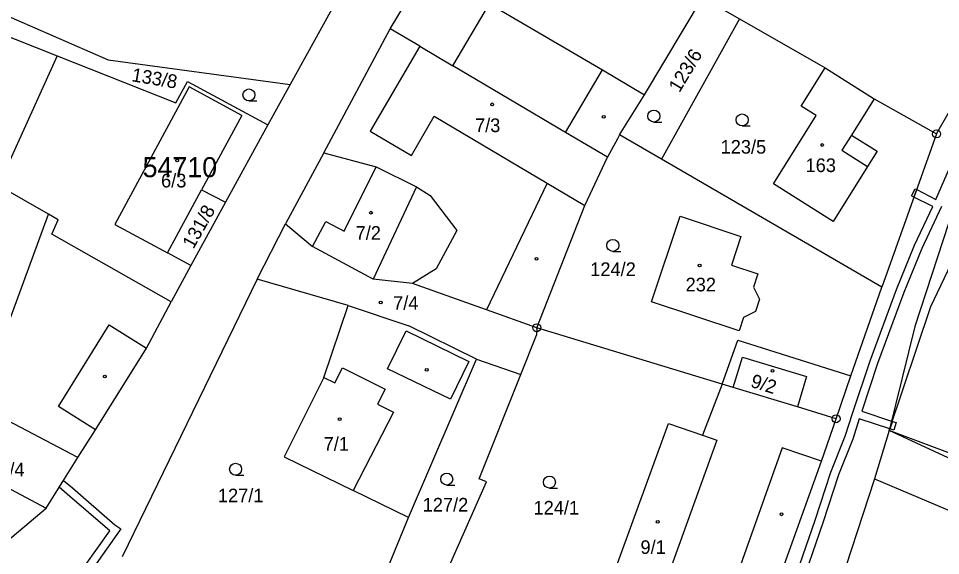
# Model space of a CAD drawing. Extents: x -747333 to -745433, y -1133152 to -1130600.
# Drawn here: x -746442.1 to -746327.1, y -1132019.6 to -1131952.5 of the extents above; entities that cross this region are included whole.
import ezdxf

# ---------------------------------------------------------------- set-up
doc = ezdxf.new("R2010")
doc.units = 0
for name, color, linetype in [('Vrstva 1', 7, 'Continuous'), ('Vrstva 18', 7, 'Continuous'), ('Vrstva 19', 7, 'Continuous'), ('Vrstva 24', 7, 'Continuous'), ('Vrstva 25', 7, 'Continuous'), ('Vrstva 3', 7, 'Continuous'), ('Vrstva 30', 7, 'Continuous'), ('Vrstva 37', 7, 'Continuous'), ('Vrstva 4', 7, 'Continuous'), ('Vrstva 53', 7, 'Continuous'), ('Vrstva 6', 7, 'Continuous'), ('Vrstva 62', 7, 'Continuous')]:
    doc.layers.add(name, color=color, linetype=linetype)

msp = doc.modelspace()

# ---------------------------------------------------------------- linework, layer by layer
at = {"layer": 'Vrstva 1'}
msp.add_line((-746311.75, -1132014.1), (-746333.47, -1132003.98), dxfattribs=at)
for points in [[(-746395.75, -1131953.81), (-746381.8, -1131930.69)], [(-746399.53, -1131945), (-746408.25, -1131960.77)], [(-746453.89, -1131947.67), (-746430.93, -1131957.68)], [(-746455.89, -1131949.78), (-746437.32, -1131957.2)], [(-746387.94, -1131958.43), (-746383.37, -1131950.7)], [(-746383.37, -1131950.7), (-746369.24, -1131958.95)], [(-746364, -1131962.05), (-746356.8, -1131949.89)], [(-746356.8, -1131949.89), (-746352.16, -1131952.55)], [(-746352.16, -1131952.55), (-746361.91, -1131970.09)], [(-746352.16, -1131952.55), (-746341.49, -1131958.67)], [(-746404.04, -1131969.28), (-746395.75, -1131953.81)], [(-746392.06, -1131955.99), (-746395.75, -1131953.81)], [(-746392.06, -1131955.99), (-746387.94, -1131958.43)], [(-746327.57, -1131966.94), (-746321.42, -1131956.19)], [(-746437.32, -1131957.2), (-746444.69, -1131973.38)], [(-746437.32, -1131957.2), (-746422.49, -1131963.07)], [(-746430.93, -1131957.68), (-746408.25, -1131960.77)], [(-746344.48, -1131963.46), (-746341.49, -1131958.67)], [(-746341.49, -1131958.67), (-746335.36, -1131962.56)], [(-746369.24, -1131958.95), (-746364, -1131962.05)], [(-746422.49, -1131963.07), (-746421.04, -1131960.39)], [(-746421.04, -1131960.39), (-746411.04, -1131965.81)], [(-746408.25, -1131960.77), (-746411.04, -1131965.81)], [(-746367.12, -1131967.06), (-746364, -1131962.05)], [(-746335.36, -1131962.56), (-746338.2, -1131967.09)], [(-746335.36, -1131962.56), (-746327.57, -1131966.94)], [(-746342.61, -1131964.63), (-746344.48, -1131963.46)], [(-746347.93, -1131973.15), (-746342.61, -1131964.63)], [(-746411.04, -1131965.81), (-746416.31, -1131975.44)], [(-746367.37, -1131967.53), (-746368.62, -1131969.86)], [(-746367.12, -1131967.06), (-746367.37, -1131967.53)], [(-746361.91, -1131970.09), (-746367.12, -1131967.06)], [(-746338.2, -1131967.09), (-746334.98, -1131969.11)], [(-746327.57, -1131966.94), (-746334.41, -1131986.06)], [(-746334.98, -1131969.11), (-746336.17, -1131971)], [(-746404.04, -1131969.28), (-746408.81, -1131978.18)], [(-746404.04, -1131969.28), (-746397.49, -1131971.05)], [(-746371.48, -1131975.87), (-746368.62, -1131969.86)], [(-746334.41, -1131986.06), (-746361.91, -1131970.09)], [(-746397.49, -1131971.05), (-746392.46, -1131973.55)], [(-746336.17, -1131971), (-746340.47, -1131977.86)], [(-746438.41, -1131976.96), (-746444.69, -1131973.38)], [(-746392.46, -1131973.55), (-746390.76, -1131974.61)], [(-746340.47, -1131977.86), (-746347.93, -1131973.15)], [(-746423.54, -1131981.79), (-746419.29, -1131973.93)], [(-746419.29, -1131973.93), (-746416.31, -1131975.44)], [(-746390.76, -1131974.61), (-746387.42, -1131978.99)], [(-746416.31, -1131975.44), (-746420.64, -1131983.36)], [(-746377.47, -1131991.14), (-746371.48, -1131975.87)], [(-746437.18, -1131977.66), (-746438.41, -1131976.96)], [(-746437.98, -1131979.44), (-746437.18, -1131977.66)], [(-746412.35, -1131985.06), (-746408.81, -1131978.18)], [(-746408.81, -1131978.18), (-746405.47, -1131981.01)], [(-746363.14, -1131987.9), (-746359.57, -1131977.21)], [(-746359.57, -1131977.21), (-746351.98, -1131979.75)], [(-746423.09, -1131987.89), (-746437.98, -1131979.44)], [(-746387.42, -1131978.99), (-746390.02, -1131983.77)], [(-746351.98, -1131979.75), (-746353.17, -1131983.31)], [(-746328.28, -1131988.49), (-746324.05, -1131979.6)], [(-746420.64, -1131983.36), (-746423.54, -1131981.79)], [(-746397.86, -1131985.09), (-746405.47, -1131981.01)], [(-746420.64, -1131983.36), (-746423.09, -1131987.89)], [(-746390.02, -1131983.77), (-746392.96, -1131985.62)], [(-746353.17, -1131983.31), (-746349.86, -1131984.42)], [(-746412.35, -1131985.06), (-746429.19, -1132019.77)], [(-746400.99, -1131988.36), (-746412.35, -1131985.06)], [(-746392.96, -1131985.62), (-746397.86, -1131985.09)], [(-746349.86, -1131984.42), (-746350.41, -1131986.06)], [(-746383.74, -1131988.91), (-746392.96, -1131985.62)], [(-746350.41, -1131986.06), (-746349.66, -1131987.58)], [(-746338.25, -1131997.16), (-746334.41, -1131986.06)], [(-746426.16, -1131993.7), (-746423.09, -1131987.89)], [(-746404.05, -1131997.34), (-746400.99, -1131988.36)], [(-746400.99, -1131988.36), (-746393.44, -1131990.91)], [(-746352.22, -1131991.54), (-746363.14, -1131987.9)], [(-746349.66, -1131987.58), (-746350.17, -1131989.11)], [(-746333.47, -1132003.98), (-746328.28, -1131988.49)], [(-746377.47, -1131991.14), (-746383.74, -1131988.91)], [(-746350.17, -1131989.11), (-746351.68, -1131989.88)], [(-746384.98, -1131995.05), (-746393.44, -1131990.91)], [(-746351.68, -1131989.88), (-746352.22, -1131991.54)], [(-746379.47, -1131997), (-746377.51, -1131992.07)], [(-746377.47, -1131991.14), (-746377.51, -1131992.07)], [(-746354.34, -1131998.17), (-746377.47, -1131991.14)], [(-746354.34, -1131998.17), (-746352.35, -1131992.71)], [(-746352.35, -1131992.71), (-746338.25, -1131997.16)], [(-746432.53, -1132003.87), (-746426.16, -1131993.7)], [(-746393.46, -1132014.85), (-746384.98, -1131995.05)], [(-746384.98, -1131995.05), (-746379.47, -1131997)], [(-746404.05, -1131997.34), (-746409, -1132007.27)], [(-746384.66, -1132010), (-746379.47, -1131997)], [(-746340.11, -1132002.51), (-746338.25, -1131997.16)], [(-746354.34, -1131998.17), (-746356.76, -1132004.57)], [(-746352.95, -1131998.59), (-746354.34, -1131998.17)], [(-746344.93, -1132001.03), (-746352.95, -1131998.59)], [(-746340.11, -1132002.51), (-746344.93, -1132001.03)], [(-746434.75, -1132007.36), (-746445.14, -1132001.9)], [(-746367.57, -1132021.06), (-746361.01, -1132003.1)], [(-746361.01, -1132003.1), (-746356.76, -1132004.57)], [(-746341.94, -1132007.79), (-746340.11, -1132002.51)], [(-746434.75, -1132007.36), (-746432.53, -1132003.87)], [(-746333.47, -1132003.98), (-746335.32, -1132010.03)], [(-746311.98, -1132012.06), (-746333.47, -1132003.98)], [(-746438.69, -1132013.68), (-746434.75, -1132007.36)], [(-746409, -1132007.27), (-746400.37, -1132011.48)], [(-746348.1, -1132024.97), (-746341.94, -1132007.79)], [(-746448.81, -1132008.32), (-746438.69, -1132013.68)], [(-746391.22, -1132027.33), (-746383.75, -1132010.4)], [(-746383.75, -1132010.4), (-746384.66, -1132010)], [(-746335.32, -1132010.03), (-746340.35, -1132025.42)], [(-746335.32, -1132010.03), (-746323.11, -1132015.17)], [(-746393.46, -1132014.85), (-746400.37, -1132011.48)], [(-746449.32, -1132022.63), (-746438.69, -1132013.68)], [(-746397.45, -1132024.58), (-746393.46, -1132014.85)]]:
    msp.add_lwpolyline(points, dxfattribs=at)
at = {"layer": 'Vrstva 24'}
for p, q in [((-746327.62, -1131966.94), (-746327.52, -1131966.94)), ((-746377.52, -1131991.14), (-746377.42, -1131991.14)), ((-746340.16, -1132002.51), (-746340.06, -1132002.51))]:
    msp.add_line(p, q, dxfattribs=at)
for centre in [(-746327.57, -1131966.94), (-746377.47, -1131991.14), (-746340.11, -1132002.51)]:
    msp.add_circle(centre, 0.499289, dxfattribs=at)
at = {"layer": 'Vrstva 25'}
for p, q in [((-746413.38, -1131962.82), (-746412.38, -1131962.82)), ((-746362.85, -1131965.46), (-746361.85, -1131965.46)), ((-746351.83, -1131965.94), (-746350.83, -1131965.94)), ((-746367.97, -1131981.61), (-746366.97, -1131981.61)), ((-746415.04, -1132009.56), (-746414.04, -1132009.56)), ((-746388.7, -1132010.79), (-746387.7, -1132010.79)), ((-746375.88, -1132011.17), (-746374.88, -1132011.17))]:
    msp.add_line(p, q, dxfattribs=at)
for centre, radius in [((-746413.38, -1131962.07), 0.75), ((-746383.02, -1131963.25), 0.174503), ((-746362.85, -1131964.71), 0.75), ((-746351.83, -1131965.19), 0.75), ((-746369.11, -1131964.8), 0.174503), ((-746341.85, -1131968.32), 0.174503), ((-746422.33, -1131970.25), 0.174503), ((-746398.15, -1131976.77), 0.174503), ((-746367.97, -1131980.86), 0.75), ((-746377.5, -1131982.53), 0.174503), ((-746357.14, -1131983.37), 0.174503), ((-746391.2, -1131996.4), 0.174503), ((-746348.05, -1131996.51), 0.174503), ((-746431.36, -1131997.23), 0.174503), ((-746402.06, -1132002.57), 0.174503), ((-746415.04, -1132008.81), 0.75), ((-746388.7, -1132010.04), 0.75), ((-746375.88, -1132010.42), 0.75), ((-746346.93, -1132014.44), 0.174503), ((-746362.37, -1132015.38), 0.174503)]:
    msp.add_circle(centre, radius, dxfattribs=at)
at = {"layer": 'Vrstva 3'}
for points in [[(-746392.06, -1131955.99), (-746398.27, -1131966.61)], [(-746392.06, -1131955.99), (-746387.94, -1131958.43)], [(-746373.86, -1131966.76), (-746387.94, -1131958.43)], [(-746344.48, -1131963.46), (-746341.49, -1131958.67)], [(-746341.49, -1131958.67), (-746335.36, -1131962.56)], [(-746420.84, -1131961.07), (-746430.12, -1131978.23)], [(-746414.26, -1131964.63), (-746420.84, -1131961.07)], [(-746335.36, -1131962.56), (-746338.2, -1131967.09)], [(-746342.61, -1131964.63), (-746344.48, -1131963.46)], [(-746414.26, -1131964.63), (-746419.29, -1131973.93)], [(-746393.11, -1131969.63), (-746390.26, -1131964.74)], [(-746390.26, -1131964.74), (-746376.15, -1131973.1)], [(-746347.93, -1131973.15), (-746342.61, -1131964.63)], [(-746398.27, -1131966.61), (-746393.11, -1131969.63)], [(-746368.62, -1131969.86), (-746373.86, -1131966.76)], [(-746338.2, -1131967.09), (-746339.38, -1131968.98)], [(-746339.38, -1131968.98), (-746336.17, -1131971)], [(-746371.48, -1131975.87), (-746368.62, -1131969.86)], [(-746401.49, -1131979.09), (-746397.49, -1131971.05)], [(-746397.49, -1131971.05), (-746392.46, -1131973.55)], [(-746336.17, -1131971), (-746340.47, -1131977.86)], [(-746438.41, -1131976.96), (-746444.69, -1131973.38)], [(-746392.46, -1131973.55), (-746397.86, -1131985.09)], [(-746376.15, -1131973.1), (-746371.48, -1131975.87)], [(-746340.47, -1131977.86), (-746347.93, -1131973.15)], [(-746423.54, -1131981.79), (-746419.29, -1131973.93)], [(-746446.26, -1131998.3), (-746438.41, -1131976.96)], [(-746430.12, -1131978.23), (-746423.54, -1131981.79)], [(-746405.47, -1131981.01), (-746403.78, -1131977.86)], [(-746403.78, -1131977.86), (-746401.49, -1131979.09)], [(-746363.14, -1131987.9), (-746359.57, -1131977.21)], [(-746359.57, -1131977.21), (-746351.98, -1131979.75)], [(-746351.98, -1131979.75), (-746353.17, -1131983.31)], [(-746397.86, -1131985.09), (-746405.47, -1131981.01)], [(-746353.17, -1131983.31), (-746349.86, -1131984.42)], [(-746349.86, -1131984.42), (-746350.41, -1131986.06)], [(-746350.41, -1131986.06), (-746349.66, -1131987.58)], [(-746352.22, -1131991.54), (-746363.14, -1131987.9)], [(-746349.66, -1131987.58), (-746350.17, -1131989.11)], [(-746350.17, -1131989.11), (-746351.68, -1131989.88)], [(-746351.68, -1131989.88), (-746352.22, -1131991.54)], [(-746352.95, -1131998.59), (-746351.8, -1131994.81)], [(-746351.8, -1131994.81), (-746343.78, -1131997.25)], [(-746402.65, -1131998.04), (-746401.71, -1131996.16)], [(-746401.71, -1131996.16), (-746396.39, -1131998.81)], [(-746404.05, -1131997.34), (-746409, -1132007.27)], [(-746404.05, -1131997.34), (-746402.65, -1131998.04)], [(-746343.78, -1131997.25), (-746344.93, -1132001.03)], [(-746396.39, -1131998.81), (-746397.32, -1132000.69)], [(-746344.93, -1132001.03), (-746352.95, -1131998.59)], [(-746397.32, -1132000.69), (-746395.34, -1132001.68)], [(-746434.75, -1132007.36), (-746445.14, -1132001.9)], [(-746395.34, -1132001.68), (-746400.37, -1132011.48)], [(-746367.57, -1132021.06), (-746361.01, -1132003.1)], [(-746361.01, -1132003.1), (-746356.76, -1132004.57)], [(-746356.76, -1132004.57), (-746354.99, -1132005.18)], [(-746354.99, -1132005.18), (-746363.4, -1132028.51)], [(-746438.69, -1132013.68), (-746434.75, -1132007.36)], [(-746409, -1132007.27), (-746400.37, -1132011.48)], [(-746448.81, -1132008.32), (-746438.69, -1132013.68)]]:
    msp.add_lwpolyline(points, dxfattribs=at)
at = {"layer": 'Vrstva 30'}
for points in [[(-746327.64, -1131975.11), (-746325.26, -1131969.58)], [(-746330.69, -1131974.68), (-746330.24, -1131973.79)], [(-746330.39, -1131974.83), (-746330.69, -1131974.68)], [(-746330.39, -1131974.83), (-746330.05, -1131973.88)], [(-746330.05, -1131973.88), (-746330.39, -1131974.83)], [(-746328.05, -1131976.02), (-746330.39, -1131974.83)], [(-746330.24, -1131973.79), (-746330.05, -1131973.88)], [(-746330.05, -1131973.88), (-746327.64, -1131975.11)], [(-746330.33, -1131980.84), (-746328.05, -1131976.02)], [(-746326.94, -1131976.01), (-746329.41, -1131981.24)], [(-746332.57, -1131986.38), (-746330.33, -1131980.84)], [(-746329.41, -1131981.24), (-746331.64, -1131986.74)], [(-746335.87, -1131995.26), (-746332.57, -1131986.38)], [(-746331.64, -1131986.74), (-746334.93, -1131995.6)], [(-746338, -1132001.74), (-746335.87, -1131995.26)], [(-746334.93, -1131995.6), (-746336.9, -1132001.58)], [(-746338.97, -1132004.7), (-746338, -1132001.74)], [(-746336.9, -1132001.58), (-746333.18, -1132002.8)], [(-746337.21, -1132002.53), (-746338.03, -1132005.04)], [(-746333.42, -1132003.77), (-746337.21, -1132002.53)], [(-746333.08, -1132002.83), (-746333.4, -1132003.78)], [(-746333.4, -1132003.78), (-746333.08, -1132002.83)], [(-746333.18, -1132002.8), (-746333.08, -1132002.83)], [(-746333.08, -1132002.83), (-746332.59, -1132002.99)], [(-746332.59, -1132002.99), (-746332.9, -1132003.94)], [(-746340.76, -1132009.16), (-746338.97, -1132004.7)], [(-746333.4, -1132003.78), (-746333.42, -1132003.77)], [(-746332.9, -1132003.94), (-746333.4, -1132003.78)], [(-746338.03, -1132005.04), (-746339.82, -1132009.5)], [(-746342.71, -1132015.19), (-746340.76, -1132009.16)], [(-746437.06, -1132011.07), (-746436.53, -1132010.21)], [(-746436.53, -1132010.21), (-746435.42, -1132011.15)], [(-746339.82, -1132009.5), (-746341.75, -1132015.49)], [(-746436.06, -1132011.91), (-746437.06, -1132011.07)], [(-746435.42, -1132011.15), (-746430.12, -1132015.75)], [(-746430.76, -1132016.51), (-746436.06, -1132011.91)], [(-746429.36, -1132016.26), (-746432.96, -1132021.32)], [(-746430.12, -1132015.75), (-746429.36, -1132016.26)], [(-746345.75, -1132023.97), (-746342.71, -1132015.19)], [(-746341.75, -1132015.49), (-746344.81, -1132024.31)], [(-746433.84, -1132020.84), (-746430.76, -1132016.51)]]:
    msp.add_lwpolyline(points, dxfattribs=at)
at = {"layer": 'Vrstva 37'}
for centre in [(-746383.02, -1131963.25), (-746341.85, -1131968.32), (-746422.33, -1131970.25), (-746398.15, -1131976.77), (-746357.14, -1131983.37), (-746348.05, -1131996.51), (-746402.06, -1132002.57), (-746362.37, -1132015.38)]:
    msp.add_circle(centre, 0.174503, dxfattribs=at)
at = {"layer": 'Vrstva 4'}
for points in [[(-746392.06, -1131955.99), (-746398.27, -1131966.61)], [(-746373.86, -1131966.76), (-746387.94, -1131958.43)], [(-746373.86, -1131966.76), (-746369.24, -1131958.95)], [(-746420.84, -1131961.07), (-746430.12, -1131978.23)], [(-746414.26, -1131964.63), (-746420.84, -1131961.07)], [(-746414.26, -1131964.63), (-746419.29, -1131973.93)], [(-746393.11, -1131969.63), (-746390.26, -1131964.74)], [(-746390.26, -1131964.74), (-746376.15, -1131973.1)], [(-746398.27, -1131966.61), (-746393.11, -1131969.63)], [(-746368.62, -1131969.86), (-746373.86, -1131966.76)], [(-746338.2, -1131967.09), (-746339.38, -1131968.98)], [(-746339.38, -1131968.98), (-746336.17, -1131971)], [(-746401.49, -1131979.09), (-746397.49, -1131971.05)], [(-746392.46, -1131973.55), (-746397.86, -1131985.09)], [(-746376.15, -1131973.1), (-746383.74, -1131988.91)], [(-746376.15, -1131973.1), (-746371.48, -1131975.87)], [(-746446.26, -1131998.3), (-746438.41, -1131976.96)], [(-746430.12, -1131978.23), (-746423.54, -1131981.79)], [(-746405.47, -1131981.01), (-746403.78, -1131977.86)], [(-746403.78, -1131977.86), (-746401.49, -1131979.09)], [(-746437.16, -1132000.97), (-746430.81, -1131990.79)], [(-746430.81, -1131990.79), (-746426.16, -1131993.7)], [(-746396.07, -1131996.26), (-746393.75, -1131991.54)], [(-746393.75, -1131991.54), (-746385.96, -1131995.34)], [(-746385.96, -1131995.34), (-746388.24, -1132000.05)], [(-746352.95, -1131998.59), (-746351.8, -1131994.81)], [(-746351.8, -1131994.81), (-746343.78, -1131997.25)], [(-746402.65, -1131998.04), (-746401.71, -1131996.16)], [(-746401.71, -1131996.16), (-746396.39, -1131998.81)], [(-746388.24, -1132000.05), (-746396.07, -1131996.26)], [(-746404.05, -1131997.34), (-746402.65, -1131998.04)], [(-746343.78, -1131997.25), (-746344.93, -1132001.03)], [(-746396.39, -1131998.81), (-746397.32, -1132000.69)], [(-746432.53, -1132003.87), (-746437.16, -1132000.97)], [(-746397.32, -1132000.69), (-746395.34, -1132001.68)], [(-746395.34, -1132001.68), (-746400.37, -1132011.48)], [(-746356.76, -1132004.57), (-746354.99, -1132005.18)], [(-746354.99, -1132005.18), (-746363.4, -1132028.51)], [(-746346.85, -1132006.12), (-746352.9, -1132023.25)], [(-746341.94, -1132007.79), (-746346.85, -1132006.12)]]:
    msp.add_lwpolyline(points, dxfattribs=at)
at = {"layer": 'Vrstva 6'}
for points in [[(-746322.55, -1131967.3), (-746330.26, -1131990.99)], [(-746330.26, -1131990.99), (-746333.47, -1132003.98)]]:
    msp.add_lwpolyline(points, dxfattribs=at)
at = {"layer": 'Vrstva 62'}
msp.add_circle((-746396.94, -1131988), 0.174503, dxfattribs=at)

# ---------------------------------------------------------------- texts
at = {"layer": 'Vrstva 18'}
for s, rotation, p in [('123/6', 59.08014, (-746359.66, -1131961.87)), ('133/8', 350.53767, (-746428.1, -1131960.35)), ('131/8', 60.76422, (-746420.31, -1131981.4))]:
    msp.add_text(s, height=1.7, rotation=rotation, dxfattribs=at).set_placement(p)
for s, p in [('123/5', (-746354.52, -1131969.4)), ('124/2', (-746370.79, -1131984.68)), ('127/1', (-746417.26, -1132012.94)), ('127/2', (-746391.7, -1132014.09)), ('124/1', (-746377.87, -1132014.47))]:
    msp.add_text(s, height=1.7, dxfattribs=at).set_placement(p)
at = {"layer": 'Vrstva 19'}
for s, p in [('7/3', (-746385.17, -1131966.71)), ('163', (-746343.92, -1131971.7)), ('6/3', (-746424.35, -1131973.62)), ('7/2', (-746400.07, -1131980.15)), ('232', (-746358.89, -1131986.6)), ('7/4', (-746395.39, -1131988.9)), ('7/1', (-746404.06, -1132006.49)), ('6/4', (-746444.54, -1132009.7)), ('9/1', (-746364.52, -1132019.39))]:
    msp.add_text(s, height=1.7, dxfattribs=at).set_placement(p)
msp.add_text('9/2', height=1.7, rotation=342.55782, dxfattribs=at).set_placement((-746350.89, -1131998.5))
at = {"layer": 'Vrstva 53'}
msp.add_text('54710', height=2.5, dxfattribs=at).set_placement((-746426.650311, -1131972.34))

doc.saveas('drawing.dxf')
